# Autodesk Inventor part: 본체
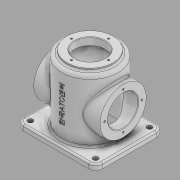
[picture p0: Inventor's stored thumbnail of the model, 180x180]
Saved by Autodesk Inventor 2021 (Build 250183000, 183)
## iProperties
Created: 2021-02
Part Number: 본체
Material: 알루미늄 6061
Document SubType Name: Modeling
Designer: 201-25
Density: 2.7 g/cm^3
Appearance: 기본값
Mass: 1235.53 g
Surface Area: 1067.61 cm^2
Volume: 457.603 cm^3
Author: 201-25
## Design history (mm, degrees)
sketch "스케치1"
  geometry: L1 (70, 60)-(-70, 60); L2 (-70, 60)-(-70, -60); L3 (-70, -60)-(70, -60); L4 (70, -60)-(70, 60); L5 (70, 60)-(-70, -60); L6 (-70, 60)-(70, -60); 1 further point
  constraints: 12 end point, 2 midpoint, 2 parallel, 1 horizontal, 1 perpendicular
  dimensions: "d0" = 140 distance of L3.end L2.end; "d1" = 120 distance of L2.end L1.end
extrude "돌출1" new body sketch "스케치1" distance "d2" = 10; taper "d3" = 0 deg
sketch "스케치2"
  geometry: C1 r 50 at (0, 0); 1 further point
  constraints: 1 centre point, 1 coincident
  dimensions: "d4" = 100 diameter of C1
extrude "돌출2" join sketch "스케치2" distance "d5" = 110; taper "d6" = 0 deg
sketch "스케치3"
  geometry: C1 r 41 at (0, 0); 1 further point
  constraints: 1 centre point, 1 coincident
  dimensions: "d7" = 82 diameter of C1
extrude "돌출3" join sketch "스케치3" distance "d8" = 5; taper "d9" = 0 deg
node "작업 평면1"
sketch "스케치4"
  geometry: L1 (0, 60)-(0, -60) reference; C1 r 41 at (60, 0); 2 further points
  constraints: 1 centre point, 1 horizontal alignment, 1 midpoint
  dimensions: "d11" = 82 diameter of C1; "d12" = 60 distance from line of L1 C1.centre
extrude "돌출4" join sketch "스케치4" stored distance "d13" = 5; taper "d14" = 0 deg
sketch "스케치5"
  geometry: C1 r 27 at (0, 0); 1 further point
  constraints: 1 centre point
  dimensions: "d15" = 54 diameter of C1
extrude "돌출5" cut sketch "스케치5" extent not by distance; stored distance "d16" = 0; taper "d17" = 0 deg
sketch "스케치6"
  geometry: C1 r 27 at (0, 0); 1 further point
  constraints: 1 centre point, 1 coincident
  dimensions: "d18" = 54 diameter of C1
extrude "돌출6" cut sketch "스케치6" extent not by distance; stored distance "d19" = 0; taper "d20" = 0 deg
sketch "스케치7"
  geometry: 1 further point
sketch "스케치8"
  geometry: A1 r 33 centre (0, 0) between (0, 33) and (-33, 0); 3 further points
  constraints: 4 point on circle, 1 centre point
  dimensions: "d21" = 66 diameter of A1
hole "구멍1" sketch "스케치8" at (0, 33), (-33, 0), (0, -33), (33, 0) diameter "d22" = 3.242; stored, may be unused: countersink angle "d26" = 90 deg, drill point angle "d28" = 118 deg; dims "d23" = 8, "d24" = 4, "d25" = 2, "d27" = 10
sketch "스케치9"
  geometry: A1 r 33 centre (0, 0) between (33, 0) and (0, 33); 3 further points
  constraints: 4 point on circle, 1 centre point, 1 coincident
  dimensions: "d29" = 66 diameter of A1
hole "구멍2" sketch "스케치9" at (0, 33), (-33, 0), (0, -33), (33, 0) diameter "d30" = 3.242; stored, may be unused: countersink angle "d34" = 90 deg, drill point angle "d36" = 118 deg; dims "d31" = 8, "d32" = 4, "d33" = 2, "d35" = 10
sketch "스케치10"
  geometry: C1 r 42 at (0, 0); 1 further point
  constraints: 1 centre point, 1 coincident
  dimensions: "d37" = 84 diameter of C1
extrude "돌출7" cut sketch "스케치10" distance "d38" = 112; taper "d39" = 0 deg
fillet "모깎기1" dims "d40" = 12
sketch "스케치11"
  geometry: A1 r 12 centre (-58, 48) between (-58, 60) and (-70, 48) reference; A2 r 12 centre (58, 48) between (70, 48) and (58, 60) reference; A3 r 12 centre (58, -48) between (58, -60) and (70, -48) reference; A4 r 12 centre (-58, -48) between (-70, -48) and (-58, -60) reference; 5 further points
  constraints: 4 coincident
hole "구멍3" sketch "스케치11" at (-58, 48), (58, 48), (58, -48), (-58, -48) diameter "d41" = 9; stored, may be unused: countersink angle "d45" = 90 deg, drill point angle "d47" = 118 deg; dims "d42" = 8, "d43" = 4, "d44" = 2, "d46" = 10
node "작업 평면2"
sketch "스케치12"
  geometry: L1 (-58, 0)-(58, 0) reference; 3 further points
  constraints: 1 midpoint, 1 vertical alignment, 1 other
  dimensions: "d49" = 66 distance from line of L1 point (0, 66)
feature "엠보싱1" sketch "스케치12" dims "d0" = 140, "d1" = 120, "d50" = 0.5, "d51" = 0
fillet "모깎기2" dims "d52" = 3
fillet "모깎기3" dims "d53" = 3
fillet "모깎기4" dims "d54" = 6
fillet "모깎기5" dims "d55" = 3
chamfer "모따기1" distance "d56" = 1; stored, may be unused: second distance "d57" = 2, angle "d58" = 45 deg
chamfer "모따기2" distance "d59" = 1; stored, may be unused: second distance "d60" = 2, angle "d61" = 45 deg
fillet "모깎기6" dims "d62" = 3
node "솔리드1"
mirror "미러1"
mirror "미러2"
feature "A9D066F2-1C7D-4E18-AEED-F7BC21143FA4" dims "d41" = 9, "d42" = 8, "d43" = 4, "d44" = 2, "d45" = 90 deg, "d46" = 10, "d47" = 118 deg
other parameters: "d10" = 59
